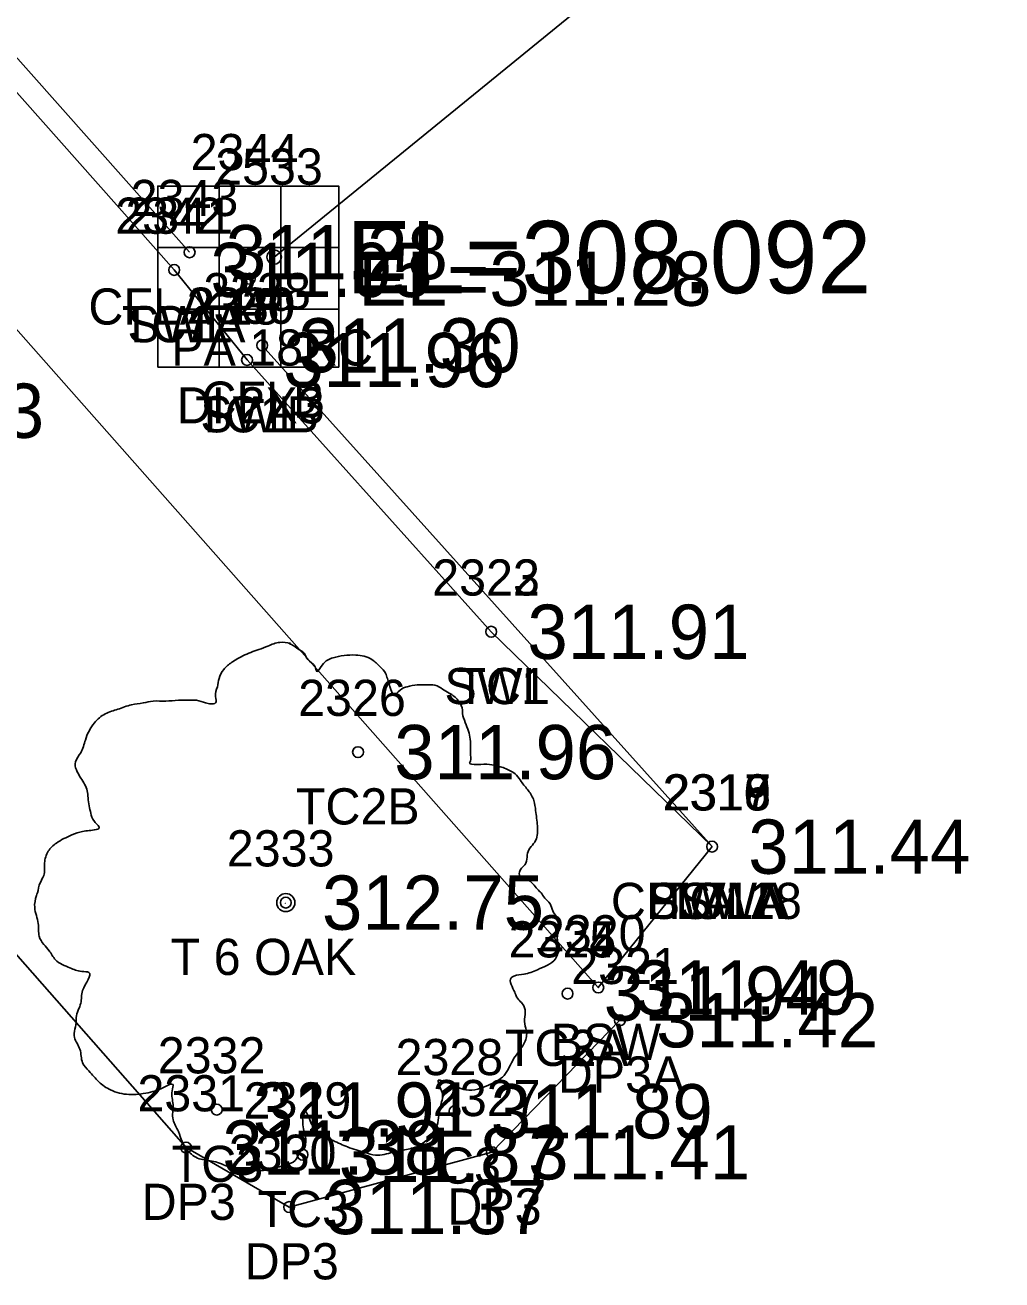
# Model space of a CAD drawing. Extents: x 1970076 to 1971136, y 803126 to 804215.
# Drawn here: x 1970384.66 to 1970411.65, y 803736.49 to 803771.17 of the extents above; entities that cross this region are included whole.
import ezdxf

# ---------------------------------------------------------------- set-up
doc = ezdxf.new("R2010")
doc.units = 0
for name, color, linetype in [('RD_EX_Conc', 7, 'Continuous'), ('RD_EX_Conc_txCode', 7, 'Continuous'), ('RD_EX_DR_Inlet', 7, 'Continuous'), ('RD_EX_DR_Inlet_txCode', 7, 'Continuous'), ('RD_EX_DR_Pipe', 7, 'Continuous'), ('RD_EX_DR_Pipe_txCode', 7, 'Continuous'), ('RD_EX_Driveway', 7, 'Continuous'), ('RD_EX_Driveway_txCode', 7, 'Continuous'), ('RD_EX_TX_Conc_ELEV', 7, 'Continuous'), ('RD_EX_TX_DR_Inlet_ELEV', 7, 'Continuous'), ('RD_EX_TX_Driveway_ELEV', 7, 'Continuous'), ('RD_EX_TX_UT_ELEV', 7, 'Continuous'), ('RD_EX_TX_VEG_ELEV', 7, 'Continuous'), ('RD_EX_VEG', 7, 'Continuous'), ('RD_EX_VEG_txCode', 7, 'Continuous'), ('RD_SMD_Locator', 7, 'Continuous'), ('RD_TX_Pipe_ElevEX', 7, 'Continuous')]:
    doc.layers.add(name, color=color, linetype=linetype)

msp = doc.modelspace()

# ---------------------------------------------------------------- linework, layer by layer
at = {"layer": 'RD_EX_Conc'}
for p, q in [((1970389.201, 803764.895), (1970371.192, 803785.158)), ((1970403.64, 803748.467), (1970391.208, 803762.321))]:
    msp.add_line(p, q, dxfattribs=at)
for points in [[(1970403.64, 803748.467), (1970397.536, 803754.406), (1970390.789, 803761.917), (1970388.776, 803764.406), (1970370.879, 803784.584), (1970367.637, 803785.738), (1970364.866, 803784.899)], [(1970403.64, 803748.467), (1970400.496, 803744.573), (1970364.866, 803784.899)]]:
    msp.add_lwpolyline(points, dxfattribs=at)
at = {"layer": 'RD_EX_DR_Inlet'}
for p, q in [((1970390.022, 803766.722), (1970390.022, 803761.722)), ((1970391.722, 803766.722), (1970391.722, 803761.722)), ((1970388.322, 803765.022), (1970393.322, 803765.022)), ((1970388.322, 803763.322), (1970393.322, 803763.322))]:
    msp.add_line(p, q, dxfattribs=at)
msp.add_lwpolyline([(1970388.322, 803761.722), (1970388.322, 803766.722), (1970393.322, 803766.722), (1970393.322, 803761.722)], close=True, dxfattribs=at)
at = {"layer": 'RD_EX_DR_Pipe'}
msp.add_line((1970391.537, 803764.762), (1970446.305, 803809.387), dxfattribs=at)
at = {"layer": 'RD_EX_Driveway'}
msp.add_lwpolyline([(1970401.094, 803743.669), (1970397.555, 803740.019), (1970391.952, 803738.507), (1970389.106, 803740.151), (1970358.957, 803774.425), (1970357.83, 803778.256), (1970359.349, 803782.137), (1970363.728, 803785.997), (1970367.42, 803786.267), (1970367.42, 803786.267), (1970371.192, 803785.158)], dxfattribs=at)
at = {"layer": 'RD_EX_VEG'}
for centre, radius in [((1970391.86, 803746.92), 0.25), ((1970391.848, 803746.901), 0.0001)]:
    msp.add_circle(centre, radius, dxfattribs=at)
for points in [[(1970391.992, 803754.087), (1970391.692, 803754.112), (1970391.367, 803754.012), (1970391.118, 803753.912), (1970390.893, 803753.837), (1970390.668, 803753.737), (1970390.368, 803753.562), (1970390.143, 803753.362), (1970390.018, 803753.112), (1970389.968, 803752.888), (1970389.918, 803752.613), (1970389.918, 803752.438), (1970389.793, 803752.413), (1970389.643, 803752.438), (1970389.393, 803752.513), (1970389.143, 803752.513), (1970388.893, 803752.513), (1970388.544, 803752.488), (1970388.194, 803752.488), (1970387.919, 803752.438), (1970387.594, 803752.388), (1970387.219, 803752.263), (1970386.869, 803752.138), (1970386.57, 803751.888), (1970386.32, 803751.413), (1970386.195, 803751.063), (1970386.045, 803750.813), (1970386.195, 803750.364), (1970386.37, 803750.014), (1970386.395, 803749.814), (1970386.47, 803749.389), (1970386.57, 803749.164), (1970386.694, 803748.964), (1970386.62, 803748.939), (1970386.245, 803748.889), (1970385.945, 803748.789), (1970385.52, 803748.564), (1970385.295, 803748.34), (1970385.195, 803748.015), (1970385.17, 803747.665), (1970385.07, 803747.465), (1970384.995, 803747.19), (1970384.97, 803747.115), (1970384.92, 803746.79), (1970385.02, 803746.34), (1970385.045, 803745.991), (1970385.17, 803745.766), (1970385.32, 803745.591), (1970385.495, 803745.341), (1970385.895, 803745.116), (1970386.22, 803745.016), (1970386.42, 803744.991), (1970386.245, 803744.491), (1970386.195, 803744.141), (1970386.07, 803743.742), (1970386.07, 803743.667), (1970386.02, 803743.192), (1970386.17, 803742.867), (1970386.245, 803742.492), (1970386.42, 803742.267), (1970386.694, 803741.967), (1970387.019, 803741.742), (1970387.519, 803741.617), (1970387.919, 803741.642), (1970388.494, 803741.817), (1970388.744, 803741.892), (1970388.719, 803741.717), (1970388.744, 803741.343), (1970388.744, 803740.918), (1970388.893, 803740.593), (1970388.993, 803740.318), (1970389.143, 803740.068), (1970389.468, 803739.843), (1970389.868, 803739.768), (1970390.293, 803739.618), (1970390.743, 803739.543), (1970391.242, 803739.518), (1970391.842, 803739.668), (1970392.117, 803739.793), (1970392.217, 803739.968), (1970392.417, 803740.343), (1970392.367, 803740.568), (1970392.392, 803741.168), (1970392.492, 803740.993), (1970392.667, 803740.643), (1970393.167, 803740.343), (1970393.566, 803740.168), (1970394.041, 803740.018), (1970394.341, 803739.943), (1970394.816, 803740.018), (1970395.191, 803740.093), (1970395.566, 803740.218), (1970395.865, 803740.493), (1970396.04, 803740.768), (1970396.09, 803741.043), (1970396.165, 803741.418), (1970396.215, 803741.592)], [(1970396.215, 803741.592), (1970396.14, 803741.767), (1970396.09, 803742.017), (1970396.165, 803741.992), (1970396.34, 803741.942), (1970396.615, 803741.817), (1970396.84, 803741.742), (1970397.165, 803741.767), (1970397.44, 803741.867), (1970397.89, 803742.142), (1970398.164, 803742.617), (1970398.439, 803743.017), (1970398.514, 803743.342), (1970398.464, 803743.567), (1970398.439, 803744.066), (1970398.239, 803744.316), (1970398.189, 803744.441), (1970398.089, 803744.841), (1970398.164, 803744.891), (1970398.439, 803744.941), (1970398.814, 803745.066), (1970399.089, 803745.191), (1970399.314, 803745.366), (1970399.389, 803745.591), (1970399.364, 803745.991), (1970399.414, 803746.39), (1970399.339, 803746.54), (1970399.239, 803746.69), (1970399.164, 803746.89), (1970399.014, 803747.04), (1970398.914, 803747.19), (1970398.814, 803747.29), (1970398.689, 803747.44), (1970398.514, 803747.565), (1970398.364, 803747.615), (1970398.314, 803747.765), (1970398.464, 803747.965), (1970398.514, 803748.065), (1970398.539, 803748.29), (1970398.764, 803748.639), (1970398.814, 803749.039), (1970398.764, 803749.464), (1970398.714, 803749.739), (1970398.564, 803750.014), (1970398.364, 803750.264), (1970398.239, 803750.439), (1970398.064, 803750.564), (1970397.74, 803750.689), (1970397.49, 803750.738), (1970397.14, 803750.738), (1970396.94, 803750.788), (1970396.965, 803750.838), (1970396.965, 803750.988), (1970396.965, 803751.263), (1970396.89, 803751.713), (1970396.74, 803752.213), (1970396.74, 803752.238), (1970396.64, 803752.488), (1970396.415, 803752.688), (1970396.24, 803752.788), (1970396.04, 803752.913), (1970395.79, 803752.938), (1970395.491, 803752.938), (1970395.216, 803752.888), (1970395.016, 803752.788), (1970394.841, 803752.663), (1970394.766, 803752.813), (1970394.666, 803753.112), (1970394.616, 803753.262), (1970394.466, 803753.437), (1970394.241, 803753.637), (1970393.791, 803753.762), (1970393.167, 803753.687), (1970392.867, 803753.487), (1970392.717, 803753.312), (1970392.667, 803753.437), (1970392.467, 803753.637), (1970392.367, 803753.812), (1970392.192, 803753.937), (1970392.042, 803754.037), (1970391.942, 803754.087)]]:
    msp.add_spline(points, degree=3, dxfattribs=at)
at = {"layer": 'RD_SMD_Locator'}
for centre, radius in [((1970389.201, 803764.895), 0.15), ((1970391.537, 803764.762), 0.2), ((1970388.776, 803764.406), 0.15), ((1970388.776, 803764.406), 0.15), ((1970390.861, 803764.164), 0.15), ((1970391.208, 803762.321), 0.15), ((1970390.789, 803761.917), 0.15), ((1970390.789, 803761.917), 0.15), ((1970397.536, 803754.406), 0.15), ((1970397.536, 803754.406), 0.15), ((1970393.856, 803751.08), 0.15), ((1970403.64, 803748.467), 0.15), ((1970403.64, 803748.467), 0.15), ((1970403.64, 803748.467), 0.15), ((1970403.64, 803748.467), 0.15), ((1970391.86, 803746.92), 0.15), ((1970400.496, 803744.573), 0.15), ((1970399.646, 803744.405), 0.15), ((1970399.646, 803744.405), 0.15), ((1970401.094, 803743.669), 0.15), ((1970389.951, 803741.2), 0.15), ((1970396.523, 803741.152), 0.15), ((1970389.106, 803740.151), 0.15), ((1970397.555, 803740.019), 0.15), ((1970392.323, 803739.953), 0.15), ((1970391.952, 803738.507), 0.15)]:
    msp.add_circle(centre, radius, dxfattribs=at)

# ---------------------------------------------------------------- texts
at = {"layer": 'RD_EX_Conc_txCode'}
for s, p in [('2343', (1970387.571, 803765.895)), ('2342', (1970387.146, 803765.406)), ('2341', (1970387.429, 803765.406)), ('2338', (1970389.578, 803763.321)), ('CFLA 18', (1970386.405, 803762.895)), ('2340', (1970389.12, 803762.917)), ('2339', (1970389.159, 803762.917)), ('TC1A', (1970387.327, 803762.406)), ('SWL', (1970387.484, 803762.406)), ('CFLB', (1970389.53, 803760.321)), ('TC1B', (1970389.356, 803759.917)), ('SWL', (1970389.498, 803759.917)), ('2322', (1970395.906, 803755.406)), ('2323', (1970395.906, 803755.406)), ('SWL', (1970396.245, 803752.406)), ('TC1', (1970396.575, 803752.406)), ('2326', (1970392.202, 803752.08)), ('2316', (1970402.27, 803749.467)), ('2317', (1970402.293, 803749.467)), ('2318', (1970402.293, 803749.467)), ('2319', (1970402.293, 803749.467)), ('TC2B', (1970392.139, 803749.08)), ('CFLA 18', (1970400.844, 803746.467)), ('SWLA', (1970401.86, 803746.467)), ('BSWA', (1970401.836, 803746.467)), ('TC1A', (1970402.191, 803746.467)), ('2324', (1970398.016, 803745.405)), ('2325', (1970398.016, 803745.405)), ('2320', (1970398.826, 803745.573)), ('BSW', (1970399.181, 803742.573)), ('TC2A', (1970397.913, 803742.405)), ('TC3A', (1970397.913, 803742.405)), ('2332', (1970388.321, 803742.2)), ('2328', (1970394.893, 803742.152)), ('2329', (1970390.693, 803740.953)), ('TC3', (1970388.707, 803739.2)), ('TC3', (1970395.279, 803739.152)), ('TC3', (1970391.079, 803737.953))]:
    msp.add_text(s, height=1, dxfattribs=at).set_placement(p)
at = {"layer": 'RD_EX_DR_Inlet_txCode'}
for s, p in [('2344', (1970389.231, 803767.164)), ('DI 2X3', (1970388.845, 803760.164))]:
    msp.add_text(s, height=1, dxfattribs=at).set_placement(p)
at = {"layer": 'RD_EX_DR_Pipe_txCode'}
for s, p in [('2533', (1970389.907, 803766.762)), ('PA 18RC', (1970388.695, 803761.762))]:
    msp.add_text(s, height=1, dxfattribs=at).set_placement(p)
at = {"layer": 'RD_EX_Driveway_txCode'}
for s, p in [('2321', (1970399.748, 803744.669)), ('DP3A', (1970399.378, 803741.669)), ('2331', (1970387.759, 803741.151)), ('2327', (1970395.925, 803741.019)), ('2330', (1970390.283, 803739.507)), ('DP3', (1970387.877, 803738.151)), ('DP3', (1970396.326, 803738.019)), ('DP3', (1970390.723, 803736.507))]:
    msp.add_text(s, height=1, dxfattribs=at).set_placement(p)
at = {"layer": 'RD_EX_TX_Conc_ELEV'}
for s, p in [('311.28', (1970390.201, 803764.145)), ('311.95', (1970389.776, 803763.656)), ('311.95', (1970389.776, 803763.656)), ('311.30', (1970392.208, 803761.571)), ('311.96', (1970391.789, 803761.167)), ('311.96', (1970391.789, 803761.167)), ('311.91', (1970398.536, 803753.656)), ('311.91', (1970398.536, 803753.656)), ('311.96', (1970394.856, 803750.33)), ('311.44', (1970404.64, 803747.717)), ('311.44', (1970404.64, 803747.717)), ('311.44', (1970404.64, 803747.717)), ('311.44', (1970404.64, 803747.717)), ('311.49', (1970401.496, 803743.823)), ('311.94', (1970400.646, 803743.655)), ('311.94', (1970400.646, 803743.655)), ('311.91', (1970390.951, 803740.45)), ('311.89', (1970397.523, 803740.402)), ('311.87', (1970393.323, 803739.203))]:
    msp.add_text(s, height=1.5, dxfattribs=at).set_placement(p)
at = {"layer": 'RD_EX_TX_DR_Inlet_ELEV'}
msp.add_text('EL=311.28', height=1.5, dxfattribs=at).set_placement((1970393.861, 803763.414))
at = {"layer": 'RD_EX_TX_Driveway_ELEV'}
for s, p in [('311.42', (1970402.094, 803742.919)), ('311.38', (1970390.106, 803739.401)), ('311.41', (1970398.555, 803739.269)), ('311.37', (1970392.952, 803737.757))]:
    msp.add_text(s, height=1.5, dxfattribs=at).set_placement(p)
at = {"layer": 'RD_EX_TX_UT_ELEV'}
msp.add_text('312.13', height=1.5, dxfattribs=at).set_placement((1970379.046, 803759.765))
at = {"layer": 'RD_EX_TX_VEG_ELEV'}
msp.add_text('312.75', height=1.5, dxfattribs=at).set_placement((1970392.86, 803746.17))
at = {"layer": 'RD_EX_VEG_txCode'}
for s, p in [('2333', (1970390.23, 803747.92)), ('T 6 OAK', (1970388.679, 803744.92))]:
    msp.add_text(s, height=1, dxfattribs=at).set_placement(p)
at = {"layer": 'RD_TX_Pipe_ElevEX'}
msp.add_text('EL=308.092', height=2, dxfattribs=at).set_placement((1970393.537, 803763.762))

doc.saveas('drawing.dxf')
